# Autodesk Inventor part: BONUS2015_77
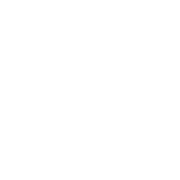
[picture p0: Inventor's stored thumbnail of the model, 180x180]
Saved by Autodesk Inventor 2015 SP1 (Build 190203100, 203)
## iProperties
Created: 2015-05
Part Number: BONUS2015_77
Material: Generisch
Document SubType Name: Modeling
Density: 1 g/cm^3
Appearance: Vorgabe
xx: 77
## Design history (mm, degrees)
